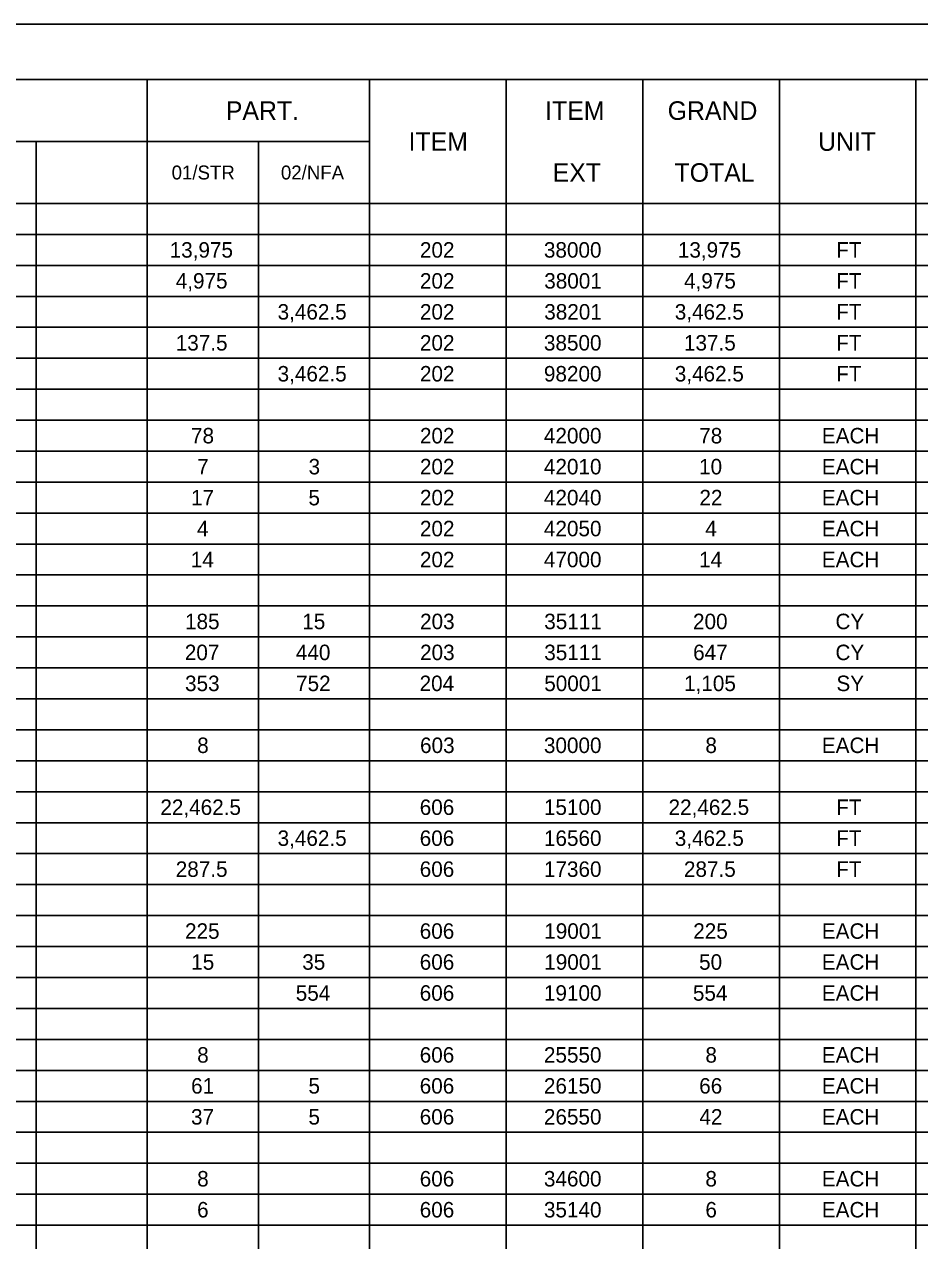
# Model space of a CAD drawing. Extents: x 0 to 34, y 0 to 22.
# Drawn here: x 8.43 to 16.52, y 11 to 22 of the extents above; entities that cross this region are included whole.
import ezdxf

# ---------------------------------------------------------------- set-up
doc = ezdxf.new("R2010")
doc.units = 0
for name, color, linetype in [('Default', 7, 'Continuous'), ('SH_Border', 7, 'Continuous'), ('SH_Cut_Line', 7, 'Continuous')]:
    doc.layers.add(name, color=color, linetype=linetype)

msp = doc.modelspace()

# ---------------------------------------------------------------- linework, layer by layer
at = {"layer": 'Default'}
for p, q in [((1.5, 21.5), (32.004, 21.5)), ((9.538, 21.5), (9.538, 0.5)), ((11.547, 21.5), (11.547, 0.5)), ((12.782, 21.5), (12.782, 0.5)), ((14.018, 21.5), (14.018, 0.5)), ((15.253, 21.5), (15.253, 0.5)), ((16.488, 21.5), (16.488, 0.5)), ((1.5, 20.94), (11.547, 20.94)), ((8.533, 20.94), (8.533, 0.5)), ((10.542, 20.94), (10.542, 0.5)), ((1.5, 20.38), (32.004, 20.38)), ((1.5, 20.1), (32.004, 20.1)), ((1.5, 19.82), (32.004, 19.82)), ((1.5, 19.54), (32.004, 19.54)), ((1.5, 19.26), (32.004, 19.26)), ((1.5, 18.98), (32.004, 18.98)), ((1.5, 18.7), (32.004, 18.7)), ((1.5, 18.42), (32.004, 18.42)), ((1.5, 18.14), (32.004, 18.14)), ((1.5, 17.86), (32.004, 17.86)), ((1.5, 17.58), (32.004, 17.58)), ((1.5, 17.3), (32.004, 17.3)), ((1.5, 17.02), (32.004, 17.02)), ((1.5, 16.74), (32.004, 16.74)), ((1.5, 16.46), (32.004, 16.46)), ((1.5, 16.18), (32.004, 16.18)), ((1.5, 15.9), (32.004, 15.9)), ((1.5, 15.62), (32.004, 15.62)), ((1.5, 15.34), (32.004, 15.34)), ((1.5, 15.06), (32.004, 15.06)), ((1.5, 14.78), (32.004, 14.78)), ((1.5, 14.5), (32.004, 14.5)), ((1.5, 14.22), (32.004, 14.22)), ((1.5, 13.94), (32.004, 13.94)), ((1.5, 13.66), (32.004, 13.66)), ((1.5, 13.38), (32.004, 13.38)), ((1.5, 13.1), (32.004, 13.1)), ((1.5, 12.82), (32.004, 12.82)), ((1.5, 12.54), (32.004, 12.54)), ((1.5, 12.26), (32.004, 12.26)), ((1.5, 11.98), (32.004, 11.98)), ((1.5, 11.7), (32.004, 11.7)), ((1.5, 11.42), (32.004, 11.42)), ((1.5, 11.14), (32.004, 11.14))]:
    msp.add_line(p, q, dxfattribs=at)
at = {"layer": 'SH_Border'}
msp.add_lwpolyline([(1.5, 21.5), (33.5, 21.5), (33.5, 0.5), (1.5, 0.5)], close=True, dxfattribs=at)
at = {"layer": 'SH_Cut_Line'}
msp.add_lwpolyline([(0, 0), (34, 0), (34, 22), (0, 22)], close=True, dxfattribs=at)

# ---------------------------------------------------------------- texts
at = {"layer": 'Default'}
for s, height, p in [('PART.', 0.168, (10.248, 21.136)), ('ITEM', 0.168, (13.135, 21.136)), ('GRAND', 0.168, (14.243, 21.136)), ('ITEM', 0.168, (11.9, 20.856)), ('UNIT', 0.168, (15.603, 20.856)), ('01/STR', 0.126, (9.758, 20.597)), ('02/NFA', 0.126, (10.746, 20.597)), ('EXT', 0.168, (13.203, 20.576)), ('TOTAL', 0.168, (14.305, 20.576)), ('13,975', 0.14, (9.74, 19.89)), ('202', 0.14, (12.003, 19.89)), ('38000', 0.14, (13.124, 19.89)), ('13,975', 0.14, (14.335, 19.89)), ('FT', 0.14, (15.767, 19.89)), ('4,975', 0.14, (9.795, 19.61)), ('202', 0.14, (12.003, 19.61)), ('38001', 0.14, (13.127, 19.61)), ('4,975', 0.14, (14.391, 19.61)), ('FT', 0.14, (15.767, 19.61)), ('3,462.5', 0.14, (10.716, 19.33)), ('202', 0.14, (12.003, 19.33)), ('38201', 0.14, (13.127, 19.33)), ('3,462.5', 0.14, (14.307, 19.33)), ('FT', 0.14, (15.767, 19.33)), ('137.5', 0.14, (9.795, 19.05)), ('202', 0.14, (12.003, 19.05)), ('38500', 0.14, (13.124, 19.05)), ('137.5', 0.14, (14.39, 19.05)), ('FT', 0.14, (15.767, 19.05)), ('3,462.5', 0.14, (10.716, 18.77)), ('202', 0.14, (12.003, 18.77)), ('98200', 0.14, (13.124, 18.77)), ('3,462.5', 0.14, (14.307, 18.77)), ('FT', 0.14, (15.767, 18.77)), ('78', 0.14, (9.933, 18.21)), ('202', 0.14, (12.003, 18.21)), ('42000', 0.14, (13.124, 18.21)), ('78', 0.14, (14.528, 18.21)), ('EACH', 0.14, (15.637, 18.21)), ('7', 0.14, (9.989, 17.93)), ('3', 0.14, (10.996, 17.93)), ('202', 0.14, (12.003, 17.93)), ('42010', 0.14, (13.124, 17.93)), ('10', 0.14, (14.527, 17.93)), ('EACH', 0.14, (15.637, 17.93)), ('17', 0.14, (9.933, 17.65)), ('5', 0.14, (10.995, 17.65)), ('202', 0.14, (12.003, 17.65)), ('42040', 0.14, (13.124, 17.65)), ('22', 0.14, (14.53, 17.65)), ('EACH', 0.14, (15.637, 17.65)), ('4', 0.14, (9.987, 17.37)), ('202', 0.14, (12.003, 17.37)), ('42050', 0.14, (13.124, 17.37)), ('4', 0.14, (14.583, 17.37)), ('EACH', 0.14, (15.637, 17.37)), ('14', 0.14, (9.931, 17.09)), ('202', 0.14, (12.003, 17.09)), ('47000', 0.14, (13.124, 17.09)), ('14', 0.14, (14.527, 17.09)), ('EACH', 0.14, (15.637, 17.09)), ('185', 0.14, (9.879, 16.53)), ('15', 0.14, (10.939, 16.53)), ('203', 0.14, (12.004, 16.53)), ('35111', 0.14, (13.127, 16.53)), ('200', 0.14, (14.472, 16.53)), ('CY', 0.14, (15.76, 16.53)), ('207', 0.14, (9.877, 16.25)), ('440', 0.14, (10.881, 16.25)), ('203', 0.14, (12.004, 16.25)), ('35111', 0.14, (13.127, 16.25)), ('647', 0.14, (14.473, 16.25)), ('CY', 0.14, (15.76, 16.25)), ('353', 0.14, (9.879, 15.97)), ('752', 0.14, (10.883, 15.97)), ('204', 0.14, (12, 15.97)), ('50001', 0.14, (13.127, 15.97)), ('1,105', 0.14, (14.391, 15.97)), ('SY', 0.14, (15.769, 15.97)), ('8', 0.14, (9.989, 15.41)), ('603', 0.14, (12.004, 15.41)), ('30000', 0.14, (13.124, 15.41)), ('8', 0.14, (14.584, 15.41)), ('EACH', 0.14, (15.637, 15.41)), ('22,462.5', 0.14, (9.656, 14.85)), ('606', 0.14, (12.001, 14.85)), ('15100', 0.14, (13.124, 14.85)), ('22,462.5', 0.14, (14.251, 14.85)), ('FT', 0.14, (15.767, 14.85)), ('3,462.5', 0.14, (10.716, 14.57)), ('606', 0.14, (12.001, 14.57)), ('16560', 0.14, (13.124, 14.57)), ('3,462.5', 0.14, (14.307, 14.57)), ('FT', 0.14, (15.767, 14.57)), ('287.5', 0.14, (9.795, 14.29)), ('606', 0.14, (12.001, 14.29)), ('17360', 0.14, (13.124, 14.29)), ('287.5', 0.14, (14.39, 14.29)), ('FT', 0.14, (15.767, 14.29)), ('225', 0.14, (9.879, 13.73)), ('606', 0.14, (12.001, 13.73)), ('19001', 0.14, (13.127, 13.73)), ('225', 0.14, (14.474, 13.73)), ('EACH', 0.14, (15.637, 13.73)), ('15', 0.14, (9.935, 13.45)), ('35', 0.14, (10.939, 13.45)), ('606', 0.14, (12.001, 13.45)), ('19001', 0.14, (13.127, 13.45)), ('50', 0.14, (14.527, 13.45)), ('EACH', 0.14, (15.637, 13.45)), ('606', 0.14, (12.001, 13.17)), ('19100', 0.14, (13.124, 13.17)), ('EACH', 0.14, (15.637, 13.17)), ('554', 0.14, (10.88, 13.17)), ('554', 0.14, (14.471, 13.17)), ('8', 0.14, (9.989, 12.61)), ('606', 0.14, (12.001, 12.61)), ('25550', 0.14, (13.124, 12.61)), ('8', 0.14, (14.584, 12.61)), ('EACH', 0.14, (15.637, 12.61)), ('61', 0.14, (9.934, 12.33)), ('5', 0.14, (10.995, 12.33)), ('606', 0.14, (12.001, 12.33)), ('26150', 0.14, (13.124, 12.33)), ('66', 0.14, (14.528, 12.33)), ('EACH', 0.14, (15.637, 12.33)), ('37', 0.14, (9.933, 12.05)), ('5', 0.14, (10.995, 12.05)), ('606', 0.14, (12.001, 12.05)), ('26550', 0.14, (13.124, 12.05)), ('42', 0.14, (14.53, 12.05)), ('EACH', 0.14, (15.637, 12.05)), ('8', 0.14, (9.989, 11.49)), ('606', 0.14, (12.001, 11.49)), ('34600', 0.14, (13.124, 11.49)), ('8', 0.14, (14.584, 11.49)), ('EACH', 0.14, (15.637, 11.49)), ('6', 0.14, (9.988, 11.21)), ('606', 0.14, (12.001, 11.21)), ('35140', 0.14, (13.124, 11.21)), ('6', 0.14, (14.584, 11.21)), ('EACH', 0.14, (15.637, 11.21))]:
    msp.add_text(s, height=height, dxfattribs=at).set_placement(p)

doc.saveas('drawing.dxf')
